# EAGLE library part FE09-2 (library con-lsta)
FEMALE HEADER
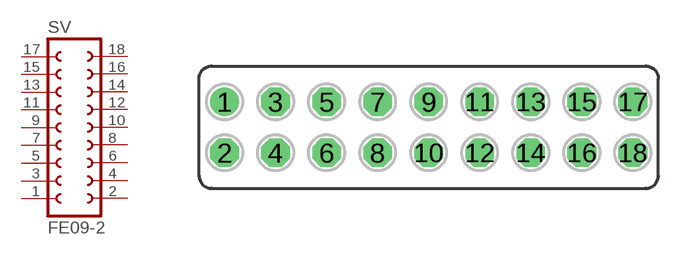
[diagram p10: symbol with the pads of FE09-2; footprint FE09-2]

Designator prefix SV

## FE09-2 (OC_FARNELL: unknown; OC_NEWARK: unknown)  [FE09-2]
1  1  pas
2  2  pas
3  3  pas
4  4  pas
5  5  pas
6  6  pas
7  7  pas
8  8  pas
9  9  pas
10  10  pas
11  11  pas
12  12  pas
13  13  pas
14  14  pas
15  15  pas
16  16  pas
17  17  pas
18  18  pas

## Footprint FE09-2 (pad centres in mm)
FEMALE HEADER
drill 0.914 round: 1 -10.16,1.27
drill 0.914 octagon: 2 -10.16,-1.27; 3 -7.62,1.27; 4 -7.62,-1.27; 5 -5.08,1.27; 6 -5.08,-1.27; 7 -2.54,1.27; 8 -2.54,-1.27; 9 0,1.27; 10 0,-1.27; 11 2.54,1.27; 12 2.54,-1.27; 13 5.08,1.27; 14 5.08,-1.27; 15 7.62,1.27; 16 7.62,-1.27; 17 10.16,1.27; 18 10.16,-1.27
